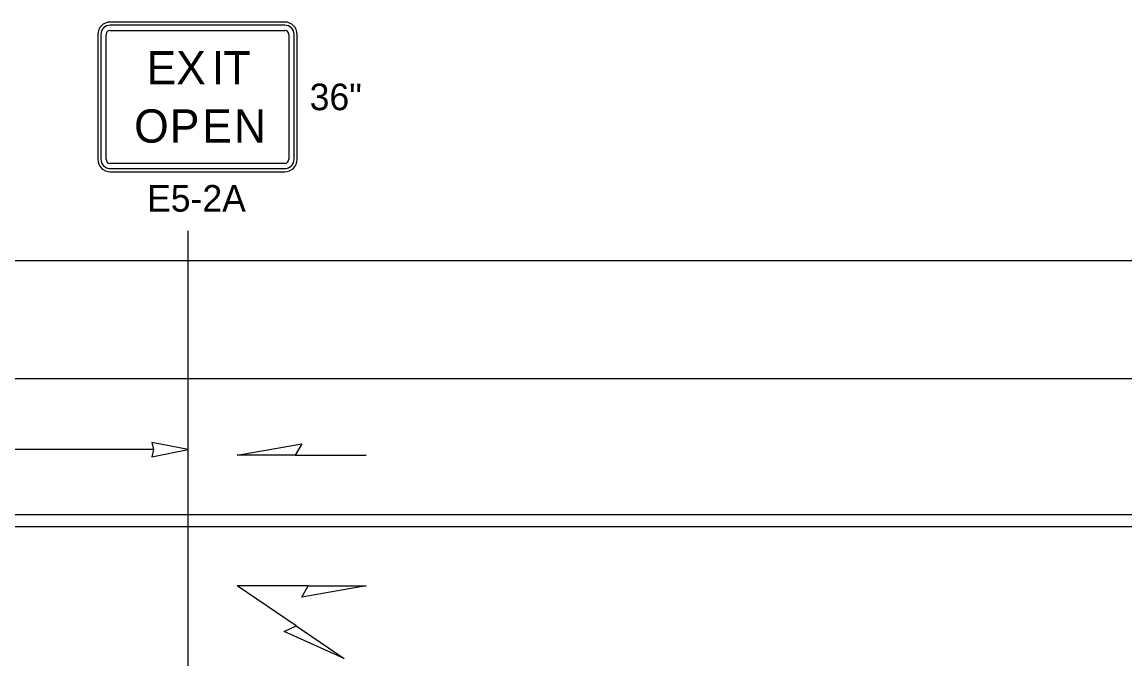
# Model space of a CAD drawing. Extents: x 99999.1 to 100055.7, y 99995 to 100013.2.
# Drawn here: x 100022.17 to 100025.157, y 100007.12 to 100008.844 of the extents above; entities that cross this region are included whole.
import ezdxf

# ---------------------------------------------------------------- set-up
doc = ezdxf.new("R2010")
doc.units = 0
for name, color, linetype in [('RD_MK_LineDblYellowCenter', 7, 'Continuous'), ('RD_MK_LineEdgeWhite', 7, 'Continuous'), ('TR_SN_ConstructionSigns', 7, 'Continuous'), ('TR_WZ_WorkZoneDetails', 7, 'Continuous')]:
    doc.layers.add(name, color=color, linetype=linetype)

msp = doc.modelspace()

# ---------------------------------------------------------------- linework, layer by layer
at = {"layer": 'RD_MK_LineDblYellowCenter'}
for p, q in [((100020.3365, 100007.5109), (100027.5715, 100007.5109)), ((100020.3035, 100007.4789), (100027.5385, 100007.4789))]:
    msp.add_line(p, q, dxfattribs=at)
at = {"layer": 'RD_MK_LineEdgeWhite'}
msp.add_line((100020.32, 100007.8789), (100027.555, 100007.8789), dxfattribs=at)
at = {"layer": 'TR_SN_ConstructionSigns'}
for p, q in [((100022.8815, 100008.8439), (100022.409, 100008.8439)), ((100022.3752, 100008.8102), (100022.3752, 100008.4727)), ((100022.3837, 100008.8102), (100022.3837, 100008.4727)), ((100022.3977, 100008.4727), (100022.3977, 100008.8102)), ((100022.8815, 100008.8355), (100022.409, 100008.8355)), ((100022.409, 100008.8214), (100022.8815, 100008.8214)), ((100022.8927, 100008.8102), (100022.8927, 100008.4727)), ((100022.9068, 100008.4727), (100022.9068, 100008.8102)), ((100022.9152, 100008.4727), (100022.9152, 100008.8102)), ((100022.8815, 100008.4614), (100022.409, 100008.4614)), ((100022.409, 100008.4473), (100022.8815, 100008.4473)), ((100022.409, 100008.4389), (100022.8815, 100008.4389))]:
    msp.add_line(p, q, dxfattribs=at)
for centre, radius, start, end in [((100022.409, 100008.8102), 0.0338, 90, 180), ((100022.8815, 100008.8102), 0.0338, 360, 90), ((100022.409, 100008.8102), 0.0253, 90, 180), ((100022.409, 100008.8102), 0.0112, 90, 180), ((100022.8815, 100008.8102), 0.0253, 360, 90), ((100022.8815, 100008.8102), 0.0112, 360, 90), ((100022.409, 100008.4727), 0.0338, 180, 270), ((100022.409, 100008.4727), 0.0253, 180, 270), ((100022.409, 100008.4727), 0.0112, 180, 270), ((100022.8815, 100008.4727), 0.0338, 270, 0), ((100022.8815, 100008.4727), 0.0253, 270, 0), ((100022.8815, 100008.4727), 0.0112, 270, 0)]:
    msp.add_arc(centre, radius, start, end, dxfattribs=at)
at = {"layer": 'TR_WZ_WorkZoneDetails'}
for p, q in [((100022.6202, 100007.0789), (100022.6202, 100008.2789)), ((100020.32, 100008.1989), (100027.555, 100008.1989)), ((100022.5265, 100007.6869), (100020.4137, 100007.6869)), ((100022.9096, 100007.6715), (100023.1024, 100007.6715)), ((100022.912, 100007.2101), (100022.7523, 100007.3183)), ((100022.9452, 100007.3183), (100022.7523, 100007.3183))]:
    msp.add_line(p, q, dxfattribs=at)
for points in [[(100022.6202, 100007.6869), (100022.5219, 100007.7062), (100022.5265, 100007.6869), (100022.5219, 100007.6676)], [(100022.7523, 100007.6715), (100022.9274, 100007.7023), (100022.9096, 100007.6715)], [(100023.1024, 100007.3183), (100022.9274, 100007.2875), (100022.9452, 100007.3183)], [(100023.0421, 100007.1219), (100022.8799, 100007.1946), (100022.912, 100007.2101)]]:
    msp.add_lwpolyline(points, close=True, dxfattribs=at)

# ---------------------------------------------------------------- texts
at = {"layer": 'TR_SN_ConstructionSigns'}
for s, height, p in [('E', 0.09, (100022.5075, 100008.6752)), ('X', 0.09, (100022.5876, 100008.6752)), ('I', 0.09, (100022.6839, 100008.6752)), ('T', 0.09, (100022.7154, 100008.6752)), ('36"', 0.072, (100022.949, 100008.6054)), ('O', 0.09, (100022.4738, 100008.5177)), ('P', 0.09, (100022.5701, 100008.5177)), ('E', 0.09, (100022.6583, 100008.5177)), ('N', 0.09, (100022.7438, 100008.5177)), ('E5-2A', 0.072, (100022.5087, 100008.3309))]:
    msp.add_text(s, height=height, rotation=360, dxfattribs=at).set_placement(p)

doc.saveas('drawing.dxf')
